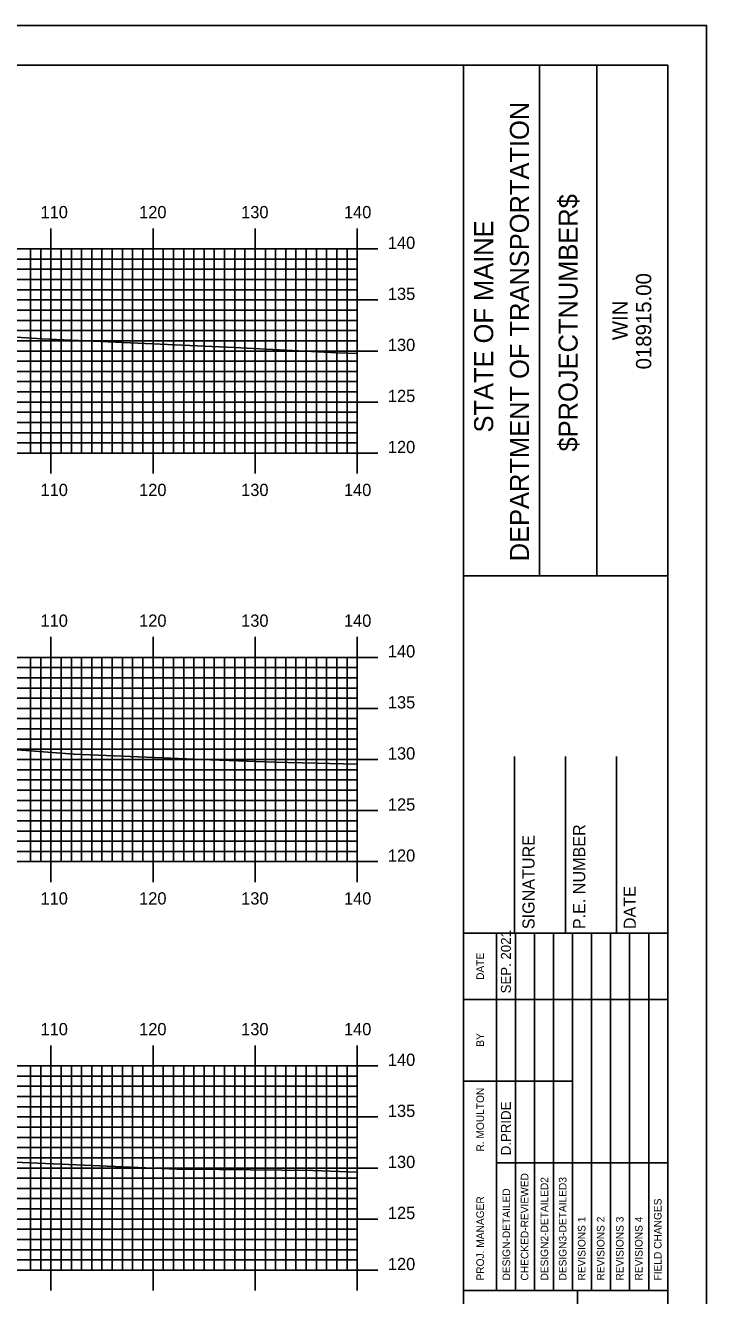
# Model space of a CAD drawing. Extents: x 841388 to 841731, y 363538 to 363758.
# Drawn here: x 841661.4 to 841728.1, y 363633.2 to 363757.6 of the extents above; entities that cross this region are included whole.
import ezdxf

# ---------------------------------------------------------------- set-up
doc = ezdxf.new("R2010")
doc.units = 0
for name, color, linetype in [('BORDER', 7, 'Continuous'), ('H_V ANNOTATION', 7, 'Continuous'), ('MAJOR', 7, 'Continuous'), ('MINOR', 7, 'Continuous'), ('PLOT BOUNDARY', 7, 'Continuous'), ('S_Roadway_Centerline', 7, 'Continuous')]:
    doc.layers.add(name, color=color, linetype=linetype)

msp = doc.modelspace()

# ---------------------------------------------------------------- linework, layer by layer
at = {"layer": 'BORDER'}
for p, q in [((841704.26, 363543.72), (841704.26, 363753.72)), ((841711.72, 363703.72), (841711.72, 363753.72)), ((841717.31, 363703.72), (841717.31, 363753.72)), ((841704.26, 363703.71), (841724.26, 363703.71)), ((841709.26, 363668.73), (841709.26, 363686.02)), ((841714.26, 363668.73), (841714.26, 363686.02)), ((841719.26, 363668.73), (841719.26, 363686.02)), ((841704.26, 363668.73), (841724.26, 363668.73)), ((841704.26, 363633.73), (841724.26, 363633.73)), ((841715.44, 363563.73), (841715.44, 363633.73))]:
    msp.add_line(p, q, dxfattribs=at)
msp.add_lwpolyline([(841404.26, 363543.72), (841724.26, 363543.72), (841724.26, 363753.72), (841404.26, 363753.72)], close=True, dxfattribs=at)
for points in [[(841707.49, 363662.23), (841707.49, 363668.73)], [(841709.35, 363633.73), (841709.35, 363668.73)], [(841711.22, 363668.73), (841711.22, 363633.73)], [(841713.08, 363633.73), (841713.08, 363668.73)], [(841714.94, 363633.73), (841714.94, 363668.73)], [(841716.81, 363633.73), (841716.81, 363668.73)], [(841718.67, 363633.73), (841718.67, 363668.73)], [(841720.53, 363633.73), (841720.53, 363668.73)], [(841722.4, 363633.73), (841722.4, 363668.73)], [(841707.49, 363633.73), (841707.49, 363667.31)], [(841704.26, 363662.23), (841724.26, 363662.23)], [(841704.26, 363654.23), (841707.49, 363654.23)], [(841707.49, 363654.23), (841714.94, 363654.23)], [(841707.49, 363646.23), (841724.26, 363646.23)]]:
    msp.add_lwpolyline(points, dxfattribs=at)
at = {"layer": 'MAJOR'}
for p, q in [((841663.86, 363737.73), (841663.86, 363735.72)), ((841673.86, 363737.73), (841673.86, 363735.72)), ((841683.86, 363737.73), (841683.86, 363735.72)), ((841693.86, 363737.73), (841693.86, 363735.72)), ((841413.86, 363735.72), (841693.86, 363735.72)), ((841413.86, 363735.72), (841693.86, 363735.72)), ((841663.86, 363715.72), (841663.86, 363735.72)), ((841673.86, 363715.72), (841673.86, 363735.72)), ((841683.86, 363715.72), (841683.86, 363735.72)), ((841695.86, 363735.72), (841691.85, 363735.72)), ((841693.86, 363715.72), (841693.86, 363735.72)), ((841693.86, 363715.72), (841693.86, 363735.72)), ((841413.86, 363730.72), (841693.86, 363730.72)), ((841695.86, 363730.72), (841691.85, 363730.72)), ((841413.86, 363725.72), (841693.86, 363725.72)), ((841695.86, 363725.72), (841691.85, 363725.72)), ((841413.86, 363720.72), (841693.86, 363720.72)), ((841695.86, 363720.72), (841691.85, 363720.72)), ((841413.86, 363715.72), (841693.86, 363715.72)), ((841413.86, 363715.72), (841693.86, 363715.72)), ((841663.86, 363713.72), (841663.86, 363715.72)), ((841673.86, 363713.72), (841673.86, 363715.72)), ((841683.86, 363713.72), (841683.86, 363715.72)), ((841695.86, 363715.72), (841691.85, 363715.72)), ((841693.86, 363713.72), (841693.86, 363715.72)), ((841663.86, 363697.73), (841663.86, 363695.72)), ((841673.86, 363697.73), (841673.86, 363695.72)), ((841683.86, 363697.73), (841683.86, 363695.72)), ((841693.86, 363697.73), (841693.86, 363695.72)), ((841413.86, 363695.72), (841693.86, 363695.72)), ((841413.86, 363695.72), (841693.86, 363695.72)), ((841663.86, 363675.72), (841663.86, 363695.72)), ((841673.86, 363675.72), (841673.86, 363695.72)), ((841683.86, 363675.72), (841683.86, 363695.72)), ((841695.86, 363695.72), (841691.85, 363695.72)), ((841693.86, 363675.72), (841693.86, 363695.72)), ((841693.86, 363675.72), (841693.86, 363695.72)), ((841413.86, 363690.72), (841693.86, 363690.72)), ((841695.86, 363690.72), (841691.85, 363690.72)), ((841413.86, 363685.72), (841693.86, 363685.72)), ((841695.86, 363685.72), (841691.85, 363685.72)), ((841413.86, 363680.72), (841693.86, 363680.72)), ((841695.86, 363680.72), (841691.85, 363680.72)), ((841413.86, 363675.72), (841693.86, 363675.72)), ((841413.86, 363675.72), (841693.86, 363675.72)), ((841663.86, 363673.72), (841663.86, 363675.72)), ((841673.86, 363673.72), (841673.86, 363675.72)), ((841683.86, 363673.72), (841683.86, 363675.72)), ((841695.86, 363675.72), (841691.85, 363675.72)), ((841693.86, 363673.72), (841693.86, 363675.72)), ((841663.86, 363657.73), (841663.86, 363655.72)), ((841673.86, 363657.73), (841673.86, 363655.72)), ((841683.86, 363657.73), (841683.86, 363655.72)), ((841693.86, 363657.73), (841693.86, 363655.72)), ((841413.86, 363655.72), (841693.86, 363655.72)), ((841413.86, 363655.72), (841693.86, 363655.72)), ((841663.86, 363635.72), (841663.86, 363655.72)), ((841673.86, 363635.72), (841673.86, 363655.72)), ((841683.86, 363635.72), (841683.86, 363655.72)), ((841695.86, 363655.72), (841691.85, 363655.72)), ((841693.86, 363635.72), (841693.86, 363655.72)), ((841693.86, 363635.72), (841693.86, 363655.72)), ((841413.86, 363650.72), (841693.86, 363650.72)), ((841695.86, 363650.72), (841691.85, 363650.72)), ((841413.86, 363645.72), (841693.86, 363645.72)), ((841695.86, 363645.72), (841691.85, 363645.72)), ((841413.86, 363640.72), (841693.86, 363640.72)), ((841695.86, 363640.72), (841691.85, 363640.72)), ((841413.86, 363635.72), (841693.86, 363635.72)), ((841413.86, 363635.72), (841693.86, 363635.72)), ((841663.86, 363633.72), (841663.86, 363635.72)), ((841673.86, 363633.72), (841673.86, 363635.72)), ((841683.86, 363633.72), (841683.86, 363635.72)), ((841695.86, 363635.72), (841691.85, 363635.72)), ((841693.86, 363633.72), (841693.86, 363635.72))]:
    msp.add_line(p, q, dxfattribs=at)
at = {"layer": 'MINOR'}
for p, q in [((841661.86, 363715.72), (841661.86, 363735.72)), ((841662.86, 363715.72), (841662.86, 363735.72)), ((841664.86, 363715.72), (841664.86, 363735.72)), ((841665.86, 363715.72), (841665.86, 363735.72)), ((841666.86, 363715.72), (841666.86, 363735.72)), ((841667.86, 363715.72), (841667.86, 363735.72)), ((841668.86, 363715.72), (841668.86, 363735.72)), ((841669.86, 363715.72), (841669.86, 363735.72)), ((841670.86, 363715.72), (841670.86, 363735.72)), ((841671.86, 363715.72), (841671.86, 363735.72)), ((841672.86, 363715.72), (841672.86, 363735.72)), ((841674.86, 363715.72), (841674.86, 363735.72)), ((841675.86, 363715.72), (841675.86, 363735.72)), ((841676.86, 363715.72), (841676.86, 363735.72)), ((841677.86, 363715.72), (841677.86, 363735.72)), ((841678.86, 363715.72), (841678.86, 363735.72)), ((841679.86, 363715.72), (841679.86, 363735.72)), ((841680.86, 363715.72), (841680.86, 363735.72)), ((841681.86, 363715.72), (841681.86, 363735.72)), ((841682.86, 363715.72), (841682.86, 363735.72)), ((841684.86, 363715.72), (841684.86, 363735.72)), ((841685.86, 363715.72), (841685.86, 363735.72)), ((841686.86, 363715.72), (841686.86, 363735.72)), ((841687.86, 363715.72), (841687.86, 363735.72)), ((841688.86, 363715.72), (841688.86, 363735.72)), ((841689.86, 363715.72), (841689.86, 363735.72)), ((841690.86, 363715.72), (841690.86, 363735.72)), ((841691.86, 363715.72), (841691.86, 363735.72)), ((841692.86, 363715.72), (841692.86, 363735.72)), ((841413.86, 363734.72), (841693.86, 363734.72)), ((841693.86, 363734.72), (841691.85, 363734.72)), ((841413.86, 363733.72), (841693.86, 363733.72)), ((841693.86, 363733.72), (841691.85, 363733.72)), ((841413.86, 363732.72), (841693.86, 363732.72)), ((841413.86, 363731.72), (841693.86, 363731.72)), ((841693.86, 363732.72), (841691.85, 363732.72)), ((841693.86, 363731.72), (841691.85, 363731.72)), ((841413.86, 363729.72), (841693.86, 363729.72)), ((841693.86, 363729.72), (841691.85, 363729.72)), ((841413.86, 363728.72), (841693.86, 363728.72)), ((841693.86, 363728.72), (841691.85, 363728.72)), ((841413.86, 363727.72), (841693.86, 363727.72)), ((841413.86, 363726.72), (841693.86, 363726.72)), ((841693.86, 363727.72), (841691.85, 363727.72)), ((841693.86, 363726.72), (841691.85, 363726.72)), ((841413.86, 363724.72), (841693.86, 363724.72)), ((841693.86, 363724.72), (841691.85, 363724.72)), ((841413.86, 363723.72), (841693.86, 363723.72)), ((841693.86, 363723.72), (841691.85, 363723.72)), ((841413.86, 363722.72), (841693.86, 363722.72)), ((841413.86, 363721.72), (841693.86, 363721.72)), ((841693.86, 363722.72), (841691.85, 363722.72)), ((841693.86, 363721.72), (841691.85, 363721.72)), ((841413.86, 363719.72), (841693.86, 363719.72)), ((841693.86, 363719.72), (841691.85, 363719.72)), ((841413.86, 363718.72), (841693.86, 363718.72)), ((841693.86, 363718.72), (841691.85, 363718.72)), ((841413.86, 363717.72), (841693.86, 363717.72)), ((841413.86, 363716.72), (841693.86, 363716.72)), ((841693.86, 363717.72), (841691.85, 363717.72)), ((841693.86, 363716.72), (841691.85, 363716.72)), ((841661.86, 363675.72), (841661.86, 363695.72)), ((841662.86, 363675.72), (841662.86, 363695.72)), ((841664.86, 363675.72), (841664.86, 363695.72)), ((841665.86, 363675.72), (841665.86, 363695.72)), ((841666.86, 363675.72), (841666.86, 363695.72)), ((841667.86, 363675.72), (841667.86, 363695.72)), ((841668.86, 363675.72), (841668.86, 363695.72)), ((841669.86, 363675.72), (841669.86, 363695.72)), ((841670.86, 363675.72), (841670.86, 363695.72)), ((841671.86, 363675.72), (841671.86, 363695.72)), ((841672.86, 363675.72), (841672.86, 363695.72)), ((841674.86, 363675.72), (841674.86, 363695.72)), ((841675.86, 363675.72), (841675.86, 363695.72)), ((841676.86, 363675.72), (841676.86, 363695.72)), ((841677.86, 363675.72), (841677.86, 363695.72)), ((841678.86, 363675.72), (841678.86, 363695.72)), ((841679.86, 363675.72), (841679.86, 363695.72)), ((841680.86, 363675.72), (841680.86, 363695.72)), ((841681.86, 363675.72), (841681.86, 363695.72)), ((841682.86, 363675.72), (841682.86, 363695.72)), ((841684.86, 363675.72), (841684.86, 363695.72)), ((841685.86, 363675.72), (841685.86, 363695.72)), ((841686.86, 363675.72), (841686.86, 363695.72)), ((841687.86, 363675.72), (841687.86, 363695.72)), ((841688.86, 363675.72), (841688.86, 363695.72)), ((841689.86, 363675.72), (841689.86, 363695.72)), ((841690.86, 363675.72), (841690.86, 363695.72)), ((841691.86, 363675.72), (841691.86, 363695.72)), ((841692.86, 363675.72), (841692.86, 363695.72)), ((841413.86, 363694.72), (841693.86, 363694.72)), ((841693.86, 363694.72), (841691.85, 363694.72)), ((841413.86, 363693.72), (841693.86, 363693.72)), ((841693.86, 363693.72), (841691.85, 363693.72)), ((841413.86, 363692.72), (841693.86, 363692.72)), ((841693.86, 363692.72), (841691.85, 363692.72)), ((841413.86, 363691.72), (841693.86, 363691.72)), ((841693.86, 363691.72), (841691.85, 363691.72)), ((841413.86, 363689.72), (841693.86, 363689.72)), ((841693.86, 363689.72), (841691.85, 363689.72)), ((841413.86, 363688.72), (841693.86, 363688.72)), ((841693.86, 363688.72), (841691.85, 363688.72)), ((841413.86, 363687.72), (841693.86, 363687.72)), ((841693.86, 363687.72), (841691.85, 363687.72)), ((841413.86, 363686.72), (841693.86, 363686.72)), ((841693.86, 363686.72), (841691.85, 363686.72)), ((841413.86, 363684.72), (841693.86, 363684.72)), ((841693.86, 363684.72), (841691.85, 363684.72)), ((841413.86, 363683.72), (841693.86, 363683.72)), ((841693.86, 363683.72), (841691.85, 363683.72)), ((841413.86, 363682.72), (841693.86, 363682.72)), ((841693.86, 363682.72), (841691.85, 363682.72)), ((841413.86, 363681.72), (841693.86, 363681.72)), ((841693.86, 363681.72), (841691.85, 363681.72)), ((841413.86, 363679.72), (841693.86, 363679.72)), ((841693.86, 363679.72), (841691.85, 363679.72)), ((841413.86, 363678.72), (841693.86, 363678.72)), ((841693.86, 363678.72), (841691.85, 363678.72)), ((841413.86, 363677.72), (841693.86, 363677.72)), ((841693.86, 363677.72), (841691.85, 363677.72)), ((841413.86, 363676.72), (841693.86, 363676.72)), ((841693.86, 363676.72), (841691.85, 363676.72)), ((841661.86, 363635.72), (841661.86, 363655.72)), ((841662.86, 363635.72), (841662.86, 363655.72)), ((841664.86, 363635.72), (841664.86, 363655.72)), ((841665.86, 363635.72), (841665.86, 363655.72)), ((841666.86, 363635.72), (841666.86, 363655.72)), ((841667.86, 363635.72), (841667.86, 363655.72)), ((841668.86, 363635.72), (841668.86, 363655.72)), ((841669.86, 363635.72), (841669.86, 363655.72)), ((841670.86, 363635.72), (841670.86, 363655.72)), ((841671.86, 363635.72), (841671.86, 363655.72)), ((841672.86, 363635.72), (841672.86, 363655.72)), ((841674.86, 363635.72), (841674.86, 363655.72)), ((841675.86, 363635.72), (841675.86, 363655.72)), ((841676.86, 363635.72), (841676.86, 363655.72)), ((841677.86, 363635.72), (841677.86, 363655.72)), ((841678.86, 363635.72), (841678.86, 363655.72)), ((841679.86, 363635.72), (841679.86, 363655.72)), ((841680.86, 363635.72), (841680.86, 363655.72)), ((841681.86, 363635.72), (841681.86, 363655.72)), ((841682.86, 363635.72), (841682.86, 363655.72)), ((841684.86, 363635.72), (841684.86, 363655.72)), ((841685.86, 363635.72), (841685.86, 363655.72)), ((841686.86, 363635.72), (841686.86, 363655.72)), ((841687.86, 363635.72), (841687.86, 363655.72)), ((841688.86, 363635.72), (841688.86, 363655.72)), ((841689.86, 363635.72), (841689.86, 363655.72)), ((841690.86, 363635.72), (841690.86, 363655.72)), ((841691.86, 363635.72), (841691.86, 363655.72)), ((841692.86, 363635.72), (841692.86, 363655.72)), ((841413.86, 363654.72), (841693.86, 363654.72)), ((841693.86, 363654.72), (841691.85, 363654.72)), ((841413.86, 363653.72), (841693.86, 363653.72)), ((841693.86, 363653.72), (841691.85, 363653.72)), ((841413.86, 363652.72), (841693.86, 363652.72)), ((841693.86, 363652.72), (841691.85, 363652.72)), ((841413.86, 363651.72), (841693.86, 363651.72)), ((841693.86, 363651.72), (841691.85, 363651.72)), ((841413.86, 363649.72), (841693.86, 363649.72)), ((841693.86, 363649.72), (841691.85, 363649.72)), ((841413.86, 363648.72), (841693.86, 363648.72)), ((841693.86, 363648.72), (841691.85, 363648.72)), ((841413.86, 363647.72), (841693.86, 363647.72)), ((841693.86, 363647.72), (841691.85, 363647.72)), ((841413.86, 363646.72), (841693.86, 363646.72)), ((841693.86, 363646.72), (841691.85, 363646.72)), ((841413.86, 363644.72), (841693.86, 363644.72)), ((841693.86, 363644.72), (841691.85, 363644.72)), ((841413.86, 363643.72), (841693.86, 363643.72)), ((841693.86, 363643.72), (841691.85, 363643.72)), ((841413.86, 363642.72), (841693.86, 363642.72)), ((841693.86, 363642.72), (841691.85, 363642.72)), ((841413.86, 363641.72), (841693.86, 363641.72)), ((841693.86, 363641.72), (841691.85, 363641.72)), ((841413.86, 363639.72), (841693.86, 363639.72)), ((841693.86, 363639.72), (841691.85, 363639.72)), ((841413.86, 363638.72), (841693.86, 363638.72)), ((841693.86, 363638.72), (841691.85, 363638.72)), ((841413.86, 363637.72), (841693.86, 363637.72)), ((841693.86, 363637.72), (841691.85, 363637.72)), ((841413.86, 363636.72), (841693.86, 363636.72)), ((841693.86, 363636.72), (841691.85, 363636.72))]:
    msp.add_line(p, q, dxfattribs=at)
at = {"layer": 'PLOT BOUNDARY'}
msp.add_lwpolyline([(841388.07, 363537.6), (841728.07, 363537.6), (841728.07, 363757.6), (841388.07, 363757.6)], close=True, dxfattribs=at)
at = {"layer": 'S_Roadway_Centerline'}
for points in [[(841584.47, 363722.78), (841595.98, 363720.78), (841597.14, 363720.73), (841598.63, 363721.14), (841609.59, 363725.38), (841614.28, 363726.83), (841624.75, 363728.3), (841627.01, 363728.73), (841627.97, 363728.77), (841628.78, 363728.71), (841645.49, 363727.83), (841658.34, 363727.19), (841663, 363726.92), (841665.12, 363726.83), (841681.82, 363726.05), (841691.88, 363725.55), (841693.86, 363725.46)], [(841593.41, 363681.67), (841597.22, 363681.28), (841624.8, 363688.73), (841626.36, 363689.18), (841626.52, 363689.21), (841626.72, 363689.2), (841626.9, 363689.19), (841628.33, 363689.1), (841666.14, 363686.25), (841679.49, 363685.69), (841685.75, 363685.46), (841693.86, 363685.27)], [(841593.7, 363642.05), (841596.73, 363641.67), (841604.05, 363644.03), (841610.89, 363645.94), (841621.24, 363646.08), (841634.53, 363647.18), (841640.16, 363647.13), (841647.39, 363646.85), (841676.2, 363645.61), (841677.3, 363645.62), (841689.52, 363645.48), (841693.86, 363645.3)]]:
    msp.add_lwpolyline(points, dxfattribs=at)

# ---------------------------------------------------------------- texts
at = {"layer": 'BORDER'}
for s, height, p in [('DEPARTMENT OF TRANSPORTATION', 1.8635, (841710.67, 363705.13)), ('$PROJECTNUMBER$', 1.8635, (841715.44, 363715.88)), ('STATE OF MAINE', 1.8635, (841707.17, 363717.74)), ('018915.00', 1.491, (841722.65, 363723.92)), ('WIN', 1.491, (841720.33, 363726.78)), ('P.E. NUMBER', 1.1811, (841716.18, 363669.11)), ('SIGNATURE', 1.181, (841711.22, 363669.11)), ('DATE', 1.181, (841721.14, 363669.11)), ('SEP. 2021', 0.969, (841708.9, 363662.82)), ('DATE', 0.743, (841706.27, 363664.14)), ('BY', 0.743, (841706.27, 363657.6)), ('R. MOULTON', 0.745, (841706.27, 363647.33)), ('D.PRIDE', 0.969, (841708.9, 363646.97)), ('CHECKED-REVIEWED', 0.7455, (841710.62, 363634.7)), ('DESIGN2-DETAILED2', 0.7455, (841712.56, 363634.7)), ('DESIGN3-DETAILED3', 0.7455, (841714.35, 363634.7)), ('DESIGN-DETAILED', 0.7455, (841708.83, 363634.7)), ('PROJ. MANAGER', 0.7455, (841706.27, 363634.7)), ('FIELD CHANGES', 0.7455, (841723.66, 363634.7)), ('REVISIONS 1', 0.7455, (841716.21, 363634.7)), ('REVISIONS 2', 0.7455, (841718.07, 363634.7)), ('REVISIONS 3', 0.7455, (841719.94, 363634.7)), ('REVISIONS 4', 0.7455, (841721.8, 363634.7))]:
    msp.add_text(s, height=height, rotation=90, dxfattribs=at).set_placement(p)
at = {"layer": 'H_V ANNOTATION'}
for s, p in [('110', (841662.84, 363738.72)), ('120', (841672.5, 363738.72)), ('130', (841682.49, 363738.72)), ('140', (841692.56, 363738.72)), ('140', (841696.86, 363735.72)), ('135', (841696.86, 363730.72)), ('130', (841696.86, 363725.72)), ('125', (841696.86, 363720.72)), ('120', (841696.86, 363715.72)), ('110', (841662.84, 363711.52)), ('120', (841672.5, 363711.52)), ('130', (841682.49, 363711.52)), ('140', (841692.56, 363711.52)), ('110', (841662.84, 363698.72)), ('120', (841672.5, 363698.72)), ('130', (841682.49, 363698.72)), ('140', (841692.56, 363698.72)), ('140', (841696.86, 363695.72)), ('135', (841696.86, 363690.72)), ('130', (841696.86, 363685.72)), ('125', (841696.86, 363680.72)), ('120', (841696.86, 363675.72)), ('110', (841662.84, 363671.52)), ('120', (841672.5, 363671.52)), ('130', (841682.49, 363671.52)), ('140', (841692.56, 363671.52)), ('110', (841662.84, 363658.72)), ('120', (841672.5, 363658.72)), ('130', (841682.49, 363658.72)), ('140', (841692.56, 363658.72)), ('140', (841696.86, 363655.72)), ('135', (841696.86, 363650.72)), ('130', (841696.86, 363645.72)), ('125', (841696.86, 363640.72)), ('120', (841696.86, 363635.72))]:
    msp.add_text(s, height=1.2, dxfattribs=at).set_placement(p)

doc.saveas('drawing.dxf')
